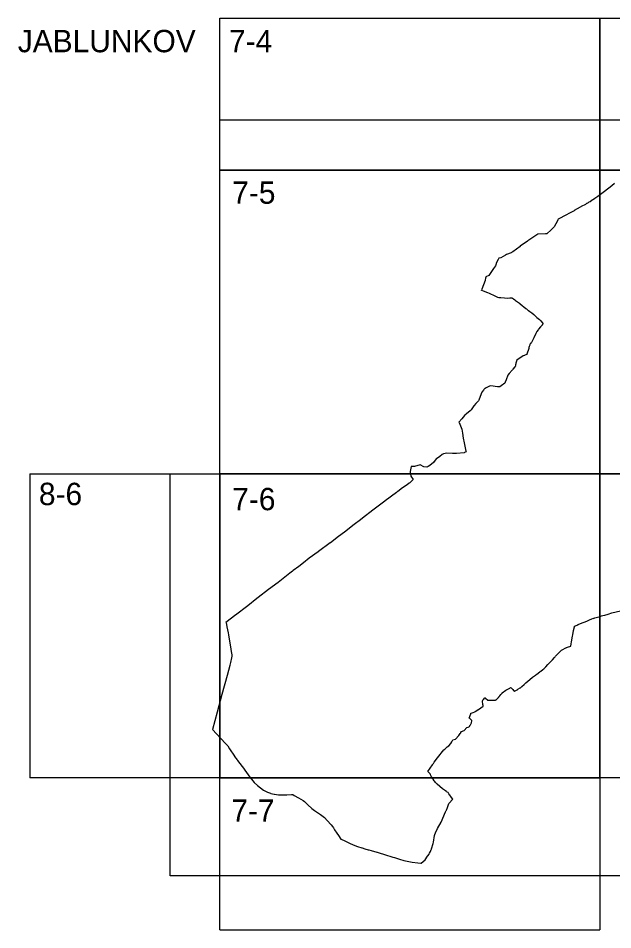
# Model space of a CAD drawing. Extents: x -449577 to -436680, y -1132317 to -1125726.
# Drawn here: x -439438.8 to -439194.4, y -1131943.6 to -1131568.6 of the extents above; entities that cross this region are included whole.
import ezdxf

# ---------------------------------------------------------------- set-up
doc = ezdxf.new("R2010")
doc.units = 0
for name, color, linetype in [('Vrstva 1', 7, 'Continuous'), ('Vrstva 10', 7, 'Continuous'), ('Vrstva 4', 7, 'Continuous')]:
    doc.layers.add(name, color=color, linetype=linetype)

msp = doc.modelspace()

# ---------------------------------------------------------------- linework, layer by layer
at = {"layer": 'Vrstva 1'}
for points in [[(-439193.65, -1131636.64), (-439194.86, -1131637.6), (-439194.86, -1131637.6), (-439196.01, -1131638.47), (-439196.58, -1131638.9), (-439197.16, -1131639.34), (-439197.32, -1131639.46), (-439199.45, -1131641.1), (-439200.52, -1131641.92), (-439200.99, -1131642.26), (-439201.75, -1131642.77), (-439202, -1131642.93), (-439202.59, -1131643.32), (-439202.63, -1131643.35), (-439202.84, -1131643.49), (-439203.75, -1131644.09), (-439203.76, -1131644.09), (-439204.23, -1131644.35), (-439204.38, -1131644.43), (-439204.56, -1131644.53), (-439205.02, -1131644.78), (-439205.2, -1131644.89), (-439205.36, -1131644.98), (-439205.46, -1131645.04), (-439205.7, -1131645.18), (-439207.36, -1131646.12), (-439207.53, -1131646.21), (-439207.76, -1131646.34), (-439210.23, -1131647.74), (-439210.35, -1131647.81), (-439212.46, -1131648.94), (-439213.48, -1131649.49), (-439216.82, -1131651.3), (-439216.99, -1131651.6), (-439217.05, -1131651.71), (-439217.83, -1131653.17), (-439218.51, -1131654.49), (-439218.65, -1131654.62), (-439218.74, -1131654.7), (-439219.88, -1131655.74), (-439221.39, -1131657.12), (-439221.56, -1131657.27), (-439221.56, -1131657.28), (-439222.03, -1131657.29), (-439225.22, -1131657.38), (-439225.23, -1131657.38), (-439225.66, -1131657.67), (-439226.49, -1131658.24), (-439228.96, -1131659.9), (-439229, -1131659.92), (-439229.24, -1131660.1), (-439229.51, -1131660.3), (-439232.49, -1131662.43), (-439232.56, -1131662.48), (-439235.56, -1131664.66), (-439236.03, -1131665), (-439236.19, -1131665.06), (-439238.13, -1131665.78), (-439238.14, -1131665.78), (-439238.53, -1131666.02), (-439240.41, -1131667.18), (-439241.33, -1131667.39), (-439241.58, -1131667.9), (-439242.34, -1131669.41), (-439242.35, -1131669.42), (-439242.42, -1131669.68), (-439242.62, -1131670.52), (-439243.45, -1131671.63), (-439244.82, -1131673.58), (-439245.38, -1131674.39), (-439245.41, -1131674.41), (-439246.57, -1131675.05), (-439246.67, -1131675.11), (-439246.74, -1131675.5), (-439246.89, -1131676.31), (-439246.94, -1131676.5), (-439248.23, -1131680.08), (-439248.4, -1131680.56), (-439248.37, -1131680.55), (-439248.35, -1131680.54), (-439247.67, -1131680.8), (-439245.86, -1131681.46), (-439245.24, -1131681.75), (-439242.95, -1131682.83), (-439242.93, -1131682.83), (-439241.77, -1131683.3), (-439241.3, -1131683.48), (-439241.27, -1131683.49), (-439240.84, -1131683.52), (-439240.7, -1131683.53), (-439240.48, -1131683.55), (-439238.88, -1131683.65), (-439237.84, -1131683.72), (-439236.79, -1131683.69), (-439235.95, -1131683.66), (-439235.94, -1131683.66), (-439235.66, -1131683.81), (-439235.29, -1131684.07), (-439234.74, -1131684.45), (-439234.35, -1131684.73), (-439232.79, -1131685.87), (-439232.62, -1131685.99), (-439231.51, -1131686.91), (-439231.12, -1131687.23), (-439230.94, -1131687.38), (-439230.19, -1131687.99), (-439229.92, -1131688.22), (-439229.32, -1131688.71), (-439229.1, -1131688.89), (-439228.46, -1131689.31), (-439227.71, -1131689.81), (-439227.68, -1131689.83), (-439226.92, -1131690.51), (-439226.04, -1131691.29), (-439225.6, -1131691.67), (-439224.59, -1131692.56), (-439224.33, -1131692.79), (-439224.28, -1131692.84), (-439224.18, -1131692.94), (-439224.17, -1131692.95), (-439224.08, -1131693.05), (-439224.05, -1131693.08), (-439223, -1131694.31), (-439223.01, -1131694.32), (-439223.45, -1131694.81), (-439223.51, -1131694.88), (-439224.08, -1131695.51), (-439224.9, -1131696.57), (-439225.07, -1131696.78), (-439225.63, -1131697.5), (-439225.93, -1131698.03), (-439225.95, -1131698.07), (-439225.96, -1131698.09), (-439226.09, -1131698.37), (-439226.89, -1131700.04), (-439227.2, -1131700.68), (-439227.82, -1131701.97), (-439227.93, -1131702.21), (-439227.94, -1131702.21), (-439227.98, -1131702.24), (-439228.27, -1131702.44), (-439228.35, -1131702.48), (-439228.4, -1131702.58), (-439228.49, -1131702.78), (-439228.58, -1131703.06), (-439228.75, -1131703.62), (-439228.76, -1131703.64), (-439228.88, -1131704.14), (-439228.9, -1131704.21), (-439228.89, -1131704.27), (-439228.88, -1131704.35), (-439228.88, -1131704.42), (-439228.89, -1131704.47), (-439229.77, -1131706.8), (-439229.79, -1131706.85), (-439229.81, -1131706.89), (-439229.82, -1131706.9), (-439230.52, -1131707.2), (-439230.77, -1131707.31), (-439231.24, -1131707.55), (-439233.85, -1131709.24), (-439233.85, -1131709.24), (-439234.22, -1131710.55), (-439234.3, -1131710.81), (-439234.41, -1131711.23), (-439234.47, -1131711.44), (-439234.47, -1131711.45), (-439234.46, -1131711.45), (-439234.29, -1131711.61), (-439234.3, -1131711.62), (-439234.66, -1131712.01), (-439235.46, -1131713.01), (-439235.47, -1131713.02), (-439235.68, -1131713.27), (-439235.68, -1131713.28), (-439235.8, -1131713.43), (-439236.96, -1131714.78), (-439237.5, -1131715.41), (-439238.26, -1131717.36), (-439238.64, -1131718.38), (-439238.77, -1131718.73), (-439240.3, -1131719.83), (-439240.92, -1131720.27), (-439241.1, -1131720.31), (-439241.12, -1131720.31), (-439241.75, -1131720.22), (-439244.59, -1131719.8), (-439245.08, -1131720.04), (-439246.41, -1131720.68), (-439246.95, -1131720.94), (-439246.98, -1131720.97), (-439247.41, -1131721.38), (-439247.58, -1131721.6), (-439248.24, -1131722.45), (-439248.24, -1131722.46), (-439248.91, -1131724.26), (-439249.48, -1131725.76), (-439249.48, -1131725.76), (-439249.62, -1131725.98), (-439249.95, -1131726.35), (-439250.67, -1131727.15), (-439251.37, -1131727.92), (-439251.38, -1131727.94), (-439251.51, -1131728.13), (-439252.58, -1131729.7), (-439253.05, -1131730.08), (-439254.62, -1131731.34), (-439255.29, -1131731.88), (-439255.39, -1131731.96), (-439255.42, -1131732), (-439256.54, -1131733.43), (-439257.68, -1131734.74), (-439257.53, -1131734.91), (-439257.52, -1131734.94), (-439257.52, -1131734.95), (-439256.51, -1131737.71), (-439256.23, -1131739.37), (-439255.91, -1131741.32), (-439255.5, -1131743.28), (-439254.77, -1131746.78), (-439254.73, -1131746.98), (-439255.38, -1131747.32), (-439255.5, -1131747.39), (-439258.67, -1131747.65), (-439258.83, -1131747.65), (-439260.32, -1131747.62), (-439262.71, -1131747.6), (-439263.99, -1131747.87), (-439264.59, -1131748.14), (-439265.57, -1131748.94), (-439266.87, -1131749.81), (-439266.96, -1131749.92), (-439268.12, -1131751.34), (-439269.57, -1131752.68), (-439270.26, -1131753), (-439270.86, -1131753.28), (-439272.03, -1131753.21), (-439273.64, -1131752.36), (-439275.88, -1131753.03), (-439277.36, -1131753), (-439277.74, -1131755.11), (-439277.75, -1131755.13), (-439277.76, -1131755.22), (-439277.47, -1131757.03), (-439276.5, -1131758.35), (-439276.49, -1131758.37), (-439277.23, -1131759.12), (-439277.84, -1131759.68), (-439278.09, -1131759.91), (-439278.89, -1131760.54), (-439280.82, -1131761.77), (-439280.88, -1131761.81), (-439282.85, -1131763.34), (-439282.91, -1131763.38), (-439283.4, -1131763.76), (-439288.06, -1131767.22), (-439288.09, -1131767.25), (-439293.04, -1131771.01), (-439297.3, -1131774.26), (-439298.18, -1131774.92), (-439300.75, -1131776.86), (-439304.75, -1131779.99), (-439307.19, -1131781.86), (-439310.5, -1131784.39), (-439310.55, -1131784.43), (-439315.34, -1131787.94), (-439315.57, -1131788.12), (-439319.18, -1131790.8), (-439321.57, -1131792.62), (-439323.54, -1131794.1), (-439325.86, -1131795.85), (-439326.09, -1131796.02), (-439327.22, -1131796.91), (-439332.04, -1131800.71), (-439335.93, -1131803.66), (-439340.15, -1131806.91), (-439341.44, -1131807.91), (-439343.83, -1131809.79), (-439345.01, -1131810.71), (-439348.95, -1131813.76), (-439349.88, -1131814.47), (-439351.12, -1131815.43), (-439353.44, -1131817.23), (-439353.44, -1131817.23), (-439353.4, -1131817.41), (-439353.11, -1131818.79), (-439353.08, -1131818.95), (-439352.55, -1131821.49), (-439352.39, -1131822.22), (-439352.39, -1131822.26), (-439351.46, -1131828.14), (-439351.45, -1131828.17), (-439351.15, -1131829.9), (-439351.15, -1131829.92), (-439351.09, -1131830.29), (-439351.03, -1131830.71), (-439351.06, -1131831.08), (-439351.21, -1131831.81), (-439351.59, -1131833.6), (-439351.88, -1131834.78), (-439351.9, -1131834.83), (-439353.01, -1131839), (-439355.11, -1131846.88), (-439357.1, -1131854.1), (-439359.03, -1131861.2), (-439359.04, -1131861.24), (-439353.76, -1131866.84), (-439352.71, -1131867.97), (-439351.95, -1131869.19), (-439349.93, -1131872.25), (-439349.88, -1131872.32), (-439348.87, -1131873.73), (-439348.71, -1131873.94), (-439346.83, -1131876.42), (-439346.26, -1131877.16), (-439346.23, -1131877.2), (-439345.71, -1131877.92), (-439344.33, -1131879.82), (-439344, -1131880.27), (-439341.85, -1131882.99), (-439340.45, -1131884.21), (-439338.05, -1131886.19), (-439336.31, -1131886.94), (-439335.12, -1131887.46), (-439334.99, -1131887.51), (-439333.66, -1131887.79), (-439333.52, -1131887.82), (-439331.9, -1131888.15), (-439331.87, -1131888.15), (-439330.91, -1131888.13), (-439330.53, -1131888.13), (-439330.01, -1131888.12), (-439329.33, -1131888.11), (-439328.42, -1131888.07), (-439326.47, -1131887.91), (-439326.02, -1131887.98), (-439325.36, -1131888.33), (-439323.64, -1131889.28), (-439321.68, -1131890.38), (-439321.16, -1131890.86), (-439320.44, -1131891.54), (-439319.64, -1131892.29), (-439318.32, -1131893.59), (-439318.18, -1131893.69), (-439316.99, -1131894.54), (-439314.58, -1131896.25), (-439312.94, -1131897.43), (-439311.89, -1131898.61), (-439310.25, -1131900.43), (-439309.61, -1131901.14), (-439309.25, -1131901.73), (-439308.79, -1131902.47), (-439307.85, -1131903.94), (-439307.22, -1131904.86), (-439306.18, -1131906.3), (-439305.11, -1131906.81), (-439303.73, -1131907.46), (-439302.42, -1131908.07), (-439300.45, -1131908.96), (-439299.32, -1131909.31), (-439297.6, -1131909.88), (-439297.45, -1131909.93), (-439296.36, -1131910.25), (-439294.94, -1131910.67), (-439294.93, -1131910.67), (-439294.72, -1131910.73), (-439294.66, -1131910.75), (-439293.8, -1131911.01), (-439291.41, -1131911.7), (-439291.29, -1131911.74), (-439290.81, -1131911.88), (-439287.88, -1131912.75), (-439285.19, -1131913.58), (-439284.85, -1131913.68), (-439284.09, -1131913.91), (-439282.08, -1131914.53), (-439280.35, -1131915.08), (-439276.89, -1131915.82)], [(-439276.89, -1131915.82), (-439274.5, -1131916.01), (-439273.3, -1131916.24), (-439273.19, -1131916.15), (-439271.61, -1131914.88), (-439270.58, -1131913.4), (-439270.47, -1131913.25), (-439269.95, -1131912.49), (-439269.84, -1131912.32), (-439269.7, -1131912.09), (-439269.32, -1131911.46), (-439269.05, -1131910.63), (-439269.03, -1131910.56), (-439269.01, -1131910.51), (-439268.98, -1131910.4), (-439268.95, -1131910.31), (-439268.95, -1131910.3), (-439268.32, -1131908.1), (-439268.18, -1131907.58), (-439267.73, -1131904.83), (-439267.73, -1131904.83), (-439267.54, -1131904.39), (-439267.28, -1131903.77), (-439266.49, -1131901.94), (-439264.92, -1131899.29), (-439263.17, -1131895.16), (-439262.85, -1131894.52), (-439262.81, -1131894.39), (-439262.42, -1131893.29), (-439261.83, -1131891.62), (-439260.15, -1131889.91), (-439261.08, -1131888.67), (-439261.14, -1131888.58), (-439261.19, -1131888.52), (-439261.22, -1131888.48), (-439261.29, -1131888.38), (-439261.34, -1131888.3), (-439261.42, -1131888.18), (-439261.78, -1131887.66), (-439262.15, -1131887.2), (-439262.72, -1131886.83), (-439262.82, -1131886.77), (-439264.47, -1131885.7), (-439266.66, -1131883.76), (-439266.79, -1131883.59), (-439266.82, -1131883.55), (-439266.9, -1131883.45), (-439267.24, -1131883.03), (-439267.57, -1131882.62), (-439267.83, -1131882.3), (-439268.31, -1131881.71), (-439268.39, -1131881.61), (-439268.89, -1131880.65), (-439269.18, -1131880.09), (-439269.41, -1131879.66), (-439269.46, -1131879.57), (-439269.5, -1131879.52), (-439269.76, -1131879.23), (-439269.96, -1131879), (-439270.22, -1131878.71), (-439270.44, -1131878.46), (-439268.58, -1131875.72), (-439268.49, -1131875.6), (-439268.17, -1131875.15), (-439267.85, -1131874.71), (-439266.52, -1131872.88), (-439263.84, -1131869.62), (-439263.49, -1131869.3), (-439262.78, -1131868.6), (-439262.67, -1131868.51), (-439262.48, -1131868.37), (-439261.88, -1131867.89), (-439261.02, -1131867.05), (-439260.61, -1131866.29), (-439260.14, -1131865.42), (-439259.09, -1131865.18), (-439257.69, -1131863.75), (-439257.15, -1131862.9), (-439257.14, -1131862.89), (-439257.14, -1131862.87), (-439256.93, -1131862.54), (-439256.88, -1131862.46), (-439256.64, -1131862.07), (-439255.48, -1131861.63), (-439254.46, -1131860.45), (-439253.93, -1131860.25), (-439253.81, -1131860.2), (-439253.39, -1131860.04), (-439253.17, -1131859.65), (-439253.12, -1131859.56), (-439252.95, -1131859.26), (-439252.54, -1131858.52), (-439252.34, -1131857.61), (-439252.34, -1131857.59), (-439252.33, -1131857.58), (-439253.38, -1131856.59), (-439253.4, -1131856.58), (-439253.41, -1131856.56), (-439253.46, -1131856.52), (-439252.81, -1131854.72), (-439252.74, -1131854.52), (-439252.58, -1131854.46), (-439251.85, -1131854.17), (-439251.16, -1131853.9), (-439251.04, -1131853.85), (-439249.83, -1131853.14), (-439249.71, -1131853.06), (-439249.71, -1131853.06), (-439249.7, -1131853.05), (-439249.58, -1131852.98), (-439247.72, -1131851.58), (-439247.72, -1131851.54), (-439247.75, -1131851.38), (-439247.82, -1131850.9), (-439247.88, -1131850.55), (-439247.98, -1131849.93), (-439248, -1131849.82), (-439248.02, -1131849.69), (-439248.04, -1131849.52), (-439248.07, -1131849.38), (-439247.53, -1131848.82), (-439246.97, -1131848.25), (-439246.93, -1131848.2), (-439246.79, -1131848.3), (-439245.79, -1131849.09), (-439245.11, -1131849.1), (-439245.05, -1131849.1), (-439244.8, -1131849.11), (-439244.64, -1131849.11), (-439243.33, -1131849.13), (-439242.7, -1131849.15), (-439242.43, -1131848.99), (-439242.4, -1131848.97), (-439242.28, -1131848.9), (-439242.14, -1131848.81), (-439242.1, -1131848.78), (-439241.56, -1131848.18), (-439241.45, -1131848.06), (-439241.36, -1131847.96), (-439241.19, -1131847.78), (-439241.11, -1131847.69), (-439241, -1131847.57), (-439240.97, -1131847.53), (-439240.94, -1131847.5), (-439240.89, -1131847.44), (-439240.8, -1131847.33), (-439240.4, -1131846.83), (-439240.19, -1131846.57), (-439239.94, -1131846.25), (-439239.83, -1131846.17), (-439238.37, -1131845.1), (-439238.16, -1131844.97), (-439236.8, -1131844.2), (-439236.4, -1131843.97), (-439236.4, -1131843.97), (-439236.26, -1131844.12), (-439235.55, -1131844.83), (-439235.18, -1131845.21), (-439235, -1131845.38), (-439234.85, -1131845.53), (-439234.76, -1131845.49), (-439233.48, -1131844.72), (-439233.39, -1131844.67), (-439232.46, -1131844.11), (-439232.42, -1131844.08), (-439232.09, -1131843.79), (-439232.04, -1131843.75), (-439231.87, -1131843.6), (-439231.86, -1131843.59), (-439231.86, -1131843.59), (-439231.82, -1131843.55), (-439231.78, -1131843.51), (-439230.89, -1131842.7), (-439230.87, -1131842.69), (-439230.28, -1131842.15), (-439230.17, -1131842.06), (-439230.06, -1131841.96), (-439230.06, -1131841.96), (-439230.05, -1131841.96), (-439230.05, -1131841.96), (-439230.05, -1131841.95), (-439230.04, -1131841.95), (-439230.03, -1131841.94), (-439230.03, -1131841.94), (-439230.02, -1131841.93), (-439230.02, -1131841.93), (-439230.01, -1131841.93), (-439230.01, -1131841.93), (-439229.43, -1131841.44), (-439227.44, -1131839.76), (-439226.24, -1131838.91), (-439226.12, -1131838.83), (-439226.07, -1131838.79), (-439226.05, -1131838.78), (-439226, -1131838.75), (-439225.64, -1131838.48), (-439224.4, -1131837.54), (-439224.22, -1131837.4), (-439224.01, -1131837.24), (-439223.99, -1131837.22), (-439223.11, -1131836.55), (-439222.76, -1131836.28), (-439222.71, -1131836.22), (-439222.62, -1131836.12), (-439221.98, -1131835.44), (-439221.08, -1131834.46), (-439219.72, -1131833.05), (-439219.5, -1131832.82), (-439219.25, -1131832.54), (-439218.41, -1131831.59), (-439218.12, -1131831.27), (-439217.92, -1131831.06), (-439217.63, -1131830.74), (-439216.45, -1131829.55), (-439215.52, -1131828.53), (-439213.46, -1131827.52), (-439213.3, -1131827.47), (-439213.1, -1131827.39), (-439211.66, -1131826.9), (-439211.51, -1131826.03), (-439211.35, -1131825.16), (-439210.93, -1131822.79), (-439210.85, -1131822.32), (-439210.52, -1131820.44), (-439210.32, -1131819.56), (-439210.29, -1131819.44), (-439210.24, -1131819.25), (-439210.23, -1131819.21), (-439210.21, -1131819.14), (-439210.2, -1131819.1), (-439210.19, -1131819.05), (-439210.18, -1131819.01), (-439210.17, -1131818.99), (-439210.11, -1131818.78), (-439209.03, -1131818.24), (-439208.74, -1131818.1), (-439208.72, -1131818.09), (-439208.47, -1131817.96), (-439208.42, -1131817.94), (-439206.65, -1131817.22), (-439206.62, -1131817.21), (-439206.59, -1131817.19), (-439205.79, -1131816.88), (-439204.83, -1131816.48), (-439204.02, -1131816.14), (-439203.08, -1131815.75), (-439203, -1131815.72), (-439202.39, -1131815.48), (-439202.54, -1131815.64), (-439202.3, -1131815.55), (-439201.81, -1131815.35), (-439201.28, -1131815.19), (-439199.58, -1131814.67), (-439198.99, -1131814.5), (-439198.54, -1131814.38), (-439197.65, -1131814.13), (-439196.34, -1131813.75), (-439194.8, -1131813.29), (-439191.26, -1131812.42)]]:
    msp.add_lwpolyline(points, dxfattribs=at)
at = {"layer": 'Vrstva 10'}
msp.add_lwpolyline([(-439043.5, -1131610.43), (-439043.5, -1131921.41), (-439376.37, -1131921.41), (-439376.37, -1131756.11), (-439356, -1131756.11), (-439356, -1131631.11), (-439356, -1131610.43), (-439043.5, -1131610.43)], dxfattribs=at)
at = {"layer": 'Vrstva 4'}
for p, q in [((-439356, -1131568.61), (-439043.5, -1131568.61)), ((-439434.13, -1131756.11), (-439434.13, -1131881.11)), ((-439356, -1131943.61), (-439199.75, -1131943.61))]:
    msp.add_line(p, q, dxfattribs=at)
for points in [[(-439199.75, -1131568.61), (-439199.75, -1131631.11), (-439356, -1131631.11), (-439356, -1131568.61)], [(-439043.5, -1131568.61), (-439043.5, -1131631.11), (-439199.75, -1131631.11), (-439199.75, -1131568.61)], [(-439434.13, -1131756.11), (-439356, -1131756.11), (-439356, -1131881.11), (-439434.13, -1131881.11)], [(-439356, -1131943.61), (-439356, -1131881.11), (-439199.75, -1131881.11), (-439199.75, -1131943.61)]]:
    msp.add_lwpolyline(points, dxfattribs=at)
for points in [[(-439199.75, -1131631.11), (-439199.75, -1131756.11), (-439356, -1131756.11), (-439356, -1131631.11)], [(-439043.5, -1131631.11), (-439043.5, -1131756.11), (-439199.75, -1131756.11), (-439199.75, -1131631.11)], [(-439199.75, -1131756.11), (-439199.75, -1131881.11), (-439356, -1131881.11), (-439356, -1131756.11)], [(-439043.5, -1131756.11), (-439043.5, -1131881.11), (-439199.75, -1131881.11), (-439199.75, -1131756.11)]]:
    msp.add_lwpolyline(points, close=True, dxfattribs=at)

# ---------------------------------------------------------------- texts
at = {"layer": 'Vrstva 1'}
for s, p in [('JABLUNKOV', (-439439.04, -1131582.61)), ('7-4', (-439352.19, -1131582.61)), ('7-5', (-439350.88, -1131644.95)), ('8-6', (-439430.35, -1131768.92)), ('7-6', (-439350.88, -1131771.02)), ('7-7', (-439351.24, -1131899.19))]:
    msp.add_text(s, height=9.2, dxfattribs=at).set_placement(p)

doc.saveas('drawing.dxf')
